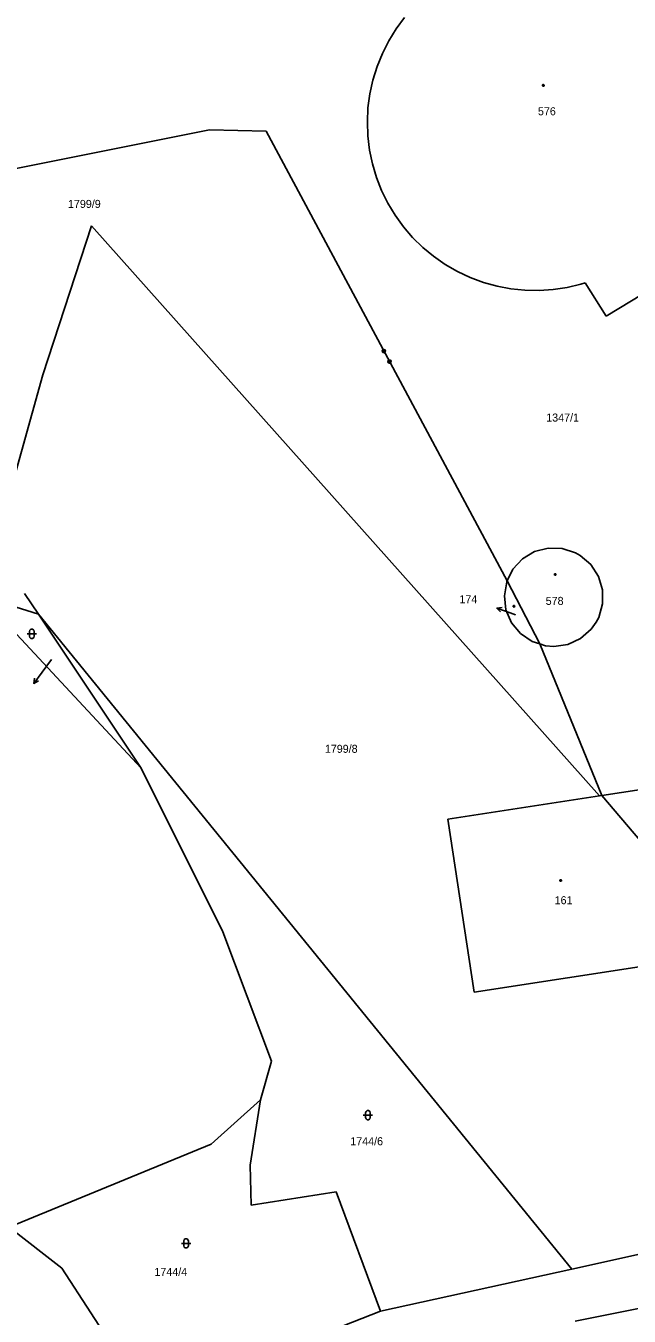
# Model space of a CAD drawing. Extents: x -747792 to -745414, y -1093712 to -1091463.
# Drawn here: x -746599.9 to -746535.8, y -1091878.7 to -1091741.7 of the extents above; entities that cross this region are included whole.
import ezdxf

# ---------------------------------------------------------------- set-up
doc = ezdxf.new("R2010")
doc.units = 0
for name, color, linetype in [('Budovy', 7, 'Continuous'), ('Doplňkové značky', 7, 'Continuous'), ('Koleje_dopravní prvky', 7, 'Continuous'), ('Ploty_opěrné zdi', 7, 'Continuous'), ('Stromy_porost', 7, 'Continuous')]:
    doc.layers.add(name, color=color, linetype=linetype)

msp = doc.modelspace()

# ---------------------------------------------------------------- linework, layer by layer
at = {"layer": 'Budovy'}
for points in [[(-746599.5, -1091806.03), (-746599.45, -1091805.89), (-746599.33, -1091805.79), (-746599.17, -1091805.79), (-746599.04, -1091805.89), (-746598.99, -1091806.03), (-746598.99, -1091806.53), (-746599.04, -1091806.68), (-746599.17, -1091806.77), (-746599.33, -1091806.77), (-746599.45, -1091806.68), (-746599.5, -1091806.53)], [(-746563.8, -1091857.14), (-746563.75, -1091856.99), (-746563.62, -1091856.9), (-746563.47, -1091856.9), (-746563.34, -1091856.99), (-746563.3, -1091857.14), (-746563.3, -1091857.64), (-746563.34, -1091857.78), (-746563.47, -1091857.88), (-746563.62, -1091857.88), (-746563.75, -1091857.78), (-746563.8, -1091857.64)], [(-746583.11, -1091870.76), (-746583.06, -1091870.61), (-746582.94, -1091870.52), (-746582.78, -1091870.52), (-746582.66, -1091870.61), (-746582.6, -1091870.76), (-746582.6, -1091871.26), (-746582.66, -1091871.41), (-746582.78, -1091871.5), (-746582.94, -1091871.5), (-746583.06, -1091871.41), (-746583.11, -1091871.26)]]:
    msp.add_lwpolyline(points, close=True, dxfattribs=at)
for points in [[(-746599.75, -1091806.28), (-746599.11, -1091806.28), (-746598.75, -1091806.28)], [(-746564.05, -1091857.39), (-746563.42, -1091857.39), (-746563.05, -1091857.39)], [(-746583.36, -1091871.01), (-746582.72, -1091871.01), (-746582.36, -1091871.01)]]:
    msp.add_lwpolyline(points, dxfattribs=at)
at = {"layer": 'Doplňkové značky'}
for points in [[(-746549.47, -1091803.94), (-746549.85, -1091803.54), (-746549.29, -1091803.47)], [(-746549.85, -1091803.54), (-746548.44, -1091804.05)], [(-746547.88, -1091804.25), (-746548.44, -1091804.05)], [(-746597.15, -1091808.99), (-746598.14, -1091810.33)], [(-746599.03, -1091811.54), (-746598.14, -1091810.33)], [(-746598.53, -1091811.28), (-746599.03, -1091811.54), (-746598.94, -1091810.99)]]:
    msp.add_lwpolyline(points, dxfattribs=at)
at = {"layer": 'Ploty_opěrné zdi'}
for points in [[(-746544.92, -1091747.95), (-746544.87, -1091747.96), (-746544.84, -1091748), (-746544.83, -1091748.03), (-746544.84, -1091748.08), (-746544.89, -1091748.11), (-746544.92, -1091748.11), (-746544.97, -1091748.1), (-746545, -1091748.07), (-746545.01, -1091748.03), (-746545, -1091747.98), (-746544.96, -1091747.95)], [(-746543.66, -1091799.89), (-746543.61, -1091799.9), (-746543.58, -1091799.94), (-746543.58, -1091799.97), (-746543.58, -1091800.02), (-746543.62, -1091800.05), (-746543.66, -1091800.05), (-746543.71, -1091800.04), (-746543.74, -1091800.01), (-746543.75, -1091799.97), (-746543.74, -1091799.92), (-746543.7, -1091799.89)], [(-746543.66, -1091799.89), (-746543.61, -1091799.9), (-746543.58, -1091799.94), (-746543.58, -1091799.97), (-746543.58, -1091800.02), (-746543.62, -1091800.05), (-746543.66, -1091800.05), (-746543.71, -1091800.04), (-746543.74, -1091800.01), (-746543.75, -1091799.97), (-746543.74, -1091799.92), (-746543.7, -1091799.89)], [(-746548.04, -1091803.27), (-746547.99, -1091803.28), (-746547.97, -1091803.32), (-746547.96, -1091803.35), (-746547.97, -1091803.4), (-746548.01, -1091803.43), (-746548.04, -1091803.44), (-746548.08, -1091803.42), (-746548.11, -1091803.39), (-746548.12, -1091803.35), (-746548.11, -1091803.31), (-746548.08, -1091803.27)], [(-746548.04, -1091803.27), (-746547.99, -1091803.28), (-746547.97, -1091803.32), (-746547.96, -1091803.35), (-746547.97, -1091803.4), (-746548.01, -1091803.43), (-746548.04, -1091803.44), (-746548.08, -1091803.42), (-746548.11, -1091803.39), (-746548.12, -1091803.35), (-746548.11, -1091803.31), (-746548.08, -1091803.27)], [(-746543.07, -1091832.39), (-746543.02, -1091832.4), (-746542.99, -1091832.44), (-746542.98, -1091832.47), (-746542.99, -1091832.52), (-746543.03, -1091832.55), (-746543.07, -1091832.55), (-746543.11, -1091832.54), (-746543.15, -1091832.51), (-746543.16, -1091832.47), (-746543.15, -1091832.42), (-746543.1, -1091832.39)], [(-746543.07, -1091832.39), (-746543.02, -1091832.4), (-746542.99, -1091832.44), (-746542.98, -1091832.47), (-746542.99, -1091832.52), (-746543.03, -1091832.55), (-746543.07, -1091832.55), (-746543.11, -1091832.54), (-746543.15, -1091832.51), (-746543.16, -1091832.47), (-746543.15, -1091832.42), (-746543.1, -1091832.39)]]:
    msp.add_lwpolyline(points, close=True, dxfattribs=at)
at = {"layer": 'Stromy_porost'}
for points in [[(-746560.55, -1091742.02), (-746559.66, -1091740.81)], [(-746561.34, -1091743.3), (-746560.55, -1091742.02)], [(-746562.01, -1091744.63), (-746561.34, -1091743.3)], [(-746562.57, -1091746.02), (-746562.01, -1091744.63)], [(-746563.02, -1091747.46), (-746562.57, -1091746.02)], [(-746563.34, -1091748.92), (-746563.02, -1091747.46)], [(-746563.54, -1091750.41), (-746563.34, -1091748.92)], [(-746563.61, -1091751.91), (-746563.54, -1091750.41)], [(-746563.55, -1091753.4), (-746563.61, -1091751.91)], [(-746632.46, -1091763.16), (-746580.36, -1091752.76)], [(-746580.36, -1091752.76), (-746574.37, -1091752.9)], [(-746574.37, -1091752.9), (-746548.76, -1091800.66)], [(-746574.37, -1091752.9), (-746548.76, -1091800.66)], [(-746563.37, -1091754.89), (-746563.55, -1091753.4)], [(-746563.06, -1091756.36), (-746563.37, -1091754.89)], [(-746562.64, -1091757.8), (-746563.06, -1091756.36)], [(-746562.09, -1091759.19), (-746562.64, -1091757.8)], [(-746561.43, -1091760.54), (-746562.09, -1091759.19)], [(-746560.65, -1091761.82), (-746561.43, -1091760.54)], [(-746559.77, -1091763.04), (-746560.65, -1091761.82)], [(-746598.08, -1091778.78), (-746592.9, -1091762.93)], [(-746538.94, -1091823.48), (-746592.9, -1091762.93)], [(-746558.8, -1091764.18), (-746559.77, -1091763.04)], [(-746557.73, -1091765.23), (-746558.8, -1091764.18)], [(-746556.57, -1091766.18), (-746557.73, -1091765.23)], [(-746555.34, -1091767.04), (-746556.57, -1091766.18)], [(-746554.04, -1091767.79), (-746555.34, -1091767.04)], [(-746552.69, -1091768.43), (-746554.04, -1091767.79)], [(-746551.28, -1091768.95), (-746552.69, -1091768.43)], [(-746549.83, -1091769.35), (-746551.28, -1091768.95)], [(-746548.36, -1091769.63), (-746549.83, -1091769.35)], [(-746546.87, -1091769.78), (-746548.36, -1091769.63)], [(-746545.37, -1091769.81), (-746546.87, -1091769.78)], [(-746543.87, -1091769.71), (-746545.37, -1091769.81)], [(-746542.39, -1091769.49), (-746543.87, -1091769.71)], [(-746540.93, -1091769.14), (-746542.39, -1091769.49)], [(-746540.49, -1091769), (-746540.93, -1091769.14)], [(-746538.24, -1091772.52), (-746540.49, -1091769)], [(-746538.24, -1091772.52), (-746533.03, -1091769.38)], [(-746561.68, -1091776.23), (-746561.72, -1091776.36), (-746561.83, -1091776.43), (-746561.96, -1091776.39), (-746562.03, -1091776.27), (-746561.99, -1091776.14), (-746561.87, -1091776.08), (-746561.74, -1091776.11), (-746561.68, -1091776.23), (-746561.7, -1091776.24), (-746561.75, -1091776.13), (-746561.81, -1091776.12), (-746561.71, -1091776.29), (-746561.73, -1091776.35), (-746561.86, -1091776.1), (-746561.9, -1091776.12), (-746561.76, -1091776.37), (-746561.8, -1091776.38), (-746561.93, -1091776.14), (-746561.97, -1091776.16), (-746561.84, -1091776.4), (-746561.89, -1091776.39), (-746561.98, -1091776.21), (-746562, -1091776.26), (-746561.94, -1091776.37)], [(-746561.68, -1091776.23), (-746561.72, -1091776.36), (-746561.83, -1091776.43), (-746561.96, -1091776.39), (-746562.03, -1091776.27), (-746561.99, -1091776.14), (-746561.87, -1091776.08), (-746561.74, -1091776.11), (-746561.68, -1091776.23), (-746561.7, -1091776.24), (-746561.75, -1091776.13), (-746561.81, -1091776.12), (-746561.71, -1091776.29), (-746561.73, -1091776.35), (-746561.86, -1091776.1), (-746561.9, -1091776.12), (-746561.76, -1091776.37), (-746561.8, -1091776.38), (-746561.93, -1091776.14), (-746561.97, -1091776.16), (-746561.84, -1091776.4), (-746561.89, -1091776.39), (-746561.98, -1091776.21), (-746562, -1091776.26), (-746561.94, -1091776.37)], [(-746561.09, -1091777.33), (-746561.12, -1091777.46), (-746561.24, -1091777.53), (-746561.37, -1091777.49), (-746561.44, -1091777.37), (-746561.4, -1091777.24), (-746561.28, -1091777.18), (-746561.15, -1091777.22), (-746561.09, -1091777.33), (-746561.11, -1091777.33), (-746561.17, -1091777.22), (-746561.22, -1091777.21), (-746561.13, -1091777.38), (-746561.14, -1091777.44), (-746561.28, -1091777.19), (-746561.31, -1091777.21), (-746561.18, -1091777.46), (-746561.21, -1091777.48), (-746561.35, -1091777.23), (-746561.38, -1091777.25), (-746561.25, -1091777.5), (-746561.3, -1091777.48), (-746561.4, -1091777.3), (-746561.41, -1091777.36), (-746561.36, -1091777.46)], [(-746561.09, -1091777.33), (-746561.12, -1091777.46), (-746561.24, -1091777.53), (-746561.37, -1091777.49), (-746561.44, -1091777.37), (-746561.4, -1091777.24), (-746561.28, -1091777.18), (-746561.15, -1091777.22), (-746561.09, -1091777.33), (-746561.11, -1091777.33), (-746561.17, -1091777.22), (-746561.22, -1091777.21), (-746561.13, -1091777.38), (-746561.14, -1091777.44), (-746561.28, -1091777.19), (-746561.31, -1091777.21), (-746561.18, -1091777.46), (-746561.21, -1091777.48), (-746561.35, -1091777.23), (-746561.38, -1091777.25), (-746561.25, -1091777.5), (-746561.3, -1091777.48), (-746561.4, -1091777.3), (-746561.41, -1091777.36), (-746561.36, -1091777.46)], [(-746603.78, -1091799.13), (-746598.08, -1091778.78)], [(-746547.14, -1091798.31), (-746545.86, -1091797.54)], [(-746545.86, -1091797.54), (-746544.42, -1091797.16)], [(-746544.42, -1091797.16), (-746542.92, -1091797.2)], [(-746542.92, -1091797.2), (-746541.5, -1091797.66)], [(-746541.5, -1091797.66), (-746541.01, -1091797.94)], [(-746548.15, -1091799.41), (-746547.14, -1091798.31)], [(-746541.01, -1091797.94), (-746539.87, -1091798.91)], [(-746539.87, -1091798.91), (-746539.06, -1091800.17)], [(-746548.76, -1091800.66), (-746548.15, -1091799.41)], [(-746539.06, -1091800.17), (-746538.63, -1091801.6)], [(-746548.81, -1091800.76), (-746549.06, -1091802.23)], [(-746548.76, -1091800.66), (-746548.81, -1091800.76)], [(-746545.3, -1091807.34), (-746548.76, -1091800.66)], [(-746545.3, -1091807.34), (-746548.76, -1091800.66)], [(-746538.63, -1091801.6), (-746538.62, -1091803.09)], [(-746587.63, -1091820.54), (-746604.66, -1091802.27)], [(-746598.54, -1091804.19), (-746604.66, -1091802.27)], [(-746600.01, -1091802), (-746598.54, -1091804.19)], [(-746548.89, -1091803.72), (-746549.06, -1091802.23)], [(-746538.62, -1091803.09), (-746539.04, -1091804.53)], [(-746598.54, -1091804.19), (-746587.63, -1091820.54)], [(-746541.9, -1091873.74), (-746598.54, -1091804.19)], [(-746548.3, -1091805.09), (-746548.89, -1091803.72)], [(-746539.04, -1091804.53), (-746539.3, -1091805.03)], [(-746547.35, -1091806.25), (-746548.3, -1091805.09)], [(-746540.97, -1091806.77), (-746539.84, -1091805.79)], [(-746539.84, -1091805.79), (-746539.3, -1091805.03)], [(-746546.11, -1091807.08), (-746547.35, -1091806.25)], [(-746545.3, -1091807.34), (-746546.11, -1091807.08)], [(-746545.3, -1091807.34), (-746538.72, -1091823.45)], [(-746545.3, -1091807.34), (-746538.72, -1091823.45)], [(-746545.3, -1091807.34), (-746544.69, -1091807.54)], [(-746542.33, -1091807.4), (-746540.97, -1091806.77)], [(-746544.69, -1091807.54), (-746543.81, -1091807.61)], [(-746543.81, -1091807.61), (-746542.33, -1091807.4)], [(-746578.94, -1091837.92), (-746587.63, -1091820.54)], [(-746530.37, -1091822.16), (-746538.72, -1091823.45)], [(-746555.07, -1091825.96), (-746538.94, -1091823.48)], [(-746538.94, -1091823.48), (-746538.72, -1091823.45)], [(-746538.72, -1091823.45), (-746533.26, -1091829.85)], [(-746538.72, -1091823.45), (-746533.26, -1091829.85)], [(-746555.07, -1091825.96), (-746552.26, -1091844.32)], [(-746578.94, -1091837.92), (-746573.8, -1091851.67)], [(-746552.26, -1091844.32), (-746532.44, -1091841.27)], [(-746573.8, -1091851.67), (-746574.94, -1091855.75)], [(-746580.21, -1091860.48), (-746574.94, -1091855.75)], [(-746574.94, -1091855.75), (-746576.07, -1091862.71)], [(-746601.63, -1091869.3), (-746580.21, -1091860.48)], [(-746576.07, -1091862.71), (-746575.96, -1091866.94)], [(-746575.96, -1091866.94), (-746566.91, -1091865.53)], [(-746566.91, -1091865.53), (-746562.21, -1091878.22)], [(-746601.63, -1091869.3), (-746596.04, -1091873.63)], [(-746522.41, -1091869.43), (-746541.9, -1091873.74)], [(-746596.04, -1091873.63), (-746586.81, -1091887.86)], [(-746562.21, -1091878.22), (-746541.9, -1091873.74)], [(-746541.55, -1091879.27), (-746516.44, -1091874.23)], [(-746562.21, -1091878.22), (-746586.81, -1091887.86)]]:
    msp.add_lwpolyline(points, dxfattribs=at)

# ---------------------------------------------------------------- texts
at = {"layer": 'Doplňkové značky'}
msp.add_text('174', height=0.85, dxfattribs=at).set_placement((-746553.83, -1091803.02))
at = {"layer": 'Koleje_dopravní prvky'}
for s, height, p in [('576', 0.85, (-746545.49, -1091751.2)), ('1799/9', 0.85, (-746595.4, -1091761.04)), ('1347/1', 0.85, (-746544.61, -1091783.73)), ('578', 0.85, (-746544.67, -1091803.2)), ('174', 0.05, (-746547.93, -1091804.25)), ('1744/7', 0.05, (-746597.26, -1091808.99)), ('1799/8', 0.85, (-746568.12, -1091818.91)), ('161', 0.85, (-746543.72, -1091834.99)), ('1744/6', 0.85, (-746565.42, -1091860.59)), ('1744/4', 0.85, (-746586.22, -1091874.46))]:
    msp.add_text(s, height=height, dxfattribs=at).set_placement(p)

doc.saveas('drawing.dxf')
